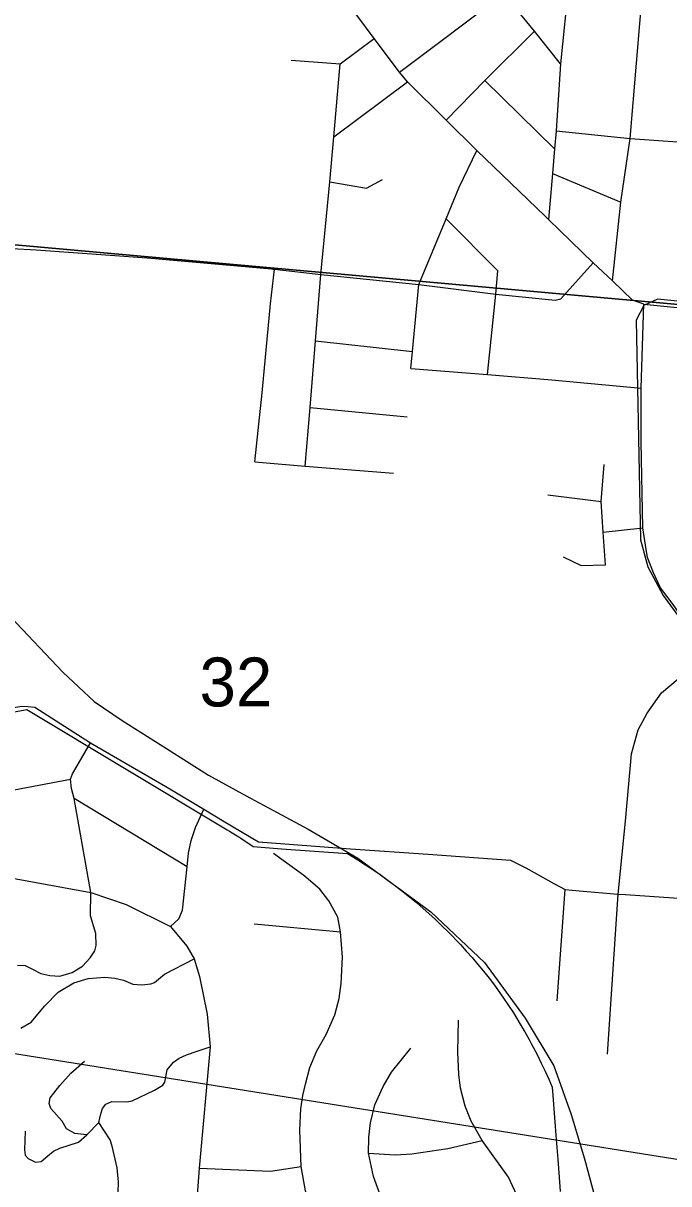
# Model space of a CAD drawing. Extents: x 0 to 34, y 0 to 22.
# Drawn here: x 7.286 to 7.838, y 16.149 to 17.141 of the extents above; entities that cross this region are included whole.
import ezdxf

# ---------------------------------------------------------------- set-up
doc = ezdxf.new("R2010")
doc.units = 0
for name, color, linetype in [('GM_X_City_Street', 7, 'Continuous'), ('GM_X_Corporation', 7, 'Continuous'), ('GM_X_County_Road', 7, 'Continuous'), ('GM_X_Rail_Line', 7, 'Continuous'), ('GM_X_Section', 7, 'Continuous'), ('GM_X_Section_Text', 7, 'Continuous'), ('GM_X_State_Route', 7, 'Continuous'), ('SH_Text', 7, 'Continuous')]:
    doc.layers.add(name, color=color, linetype=linetype)

msp = doc.modelspace()

# ---------------------------------------------------------------- linework, layer by layer
at = {"layer": 'GM_X_City_Street'}
for p, q in [((7.51532, 17.10956), (7.55715, 17.10645)), ((7.55199, 17.04406), (7.61492, 17.09112)), ((7.68107, 17.09212), (7.74065, 17.03371)), ((7.7388, 17.01252), (7.79727, 16.98814)), ((7.53616, 16.86947), (7.61911, 16.86058)), ((7.53157, 16.81266), (7.61446, 16.8047)), ((7.73481, 16.73799), (7.78045, 16.73214)), ((7.78205, 16.70614), (7.81605, 16.70967)), ((7.42639, 16.41983), (7.32984, 16.47827)), ((7.74284, 16.30544), (7.74954, 16.40042)), ((7.48369, 16.37107), (7.55766, 16.36424))]:
    msp.add_line(p, q, dxfattribs=at)
for points in [[(7.74582, 17.10655), (7.72338, 17.13426), (7.69725, 17.16653), (7.65761, 17.21715), (7.62474, 17.25859), (7.61315, 17.27463), (7.59254, 17.29971), (7.58023, 17.31598), (7.55509, 17.34949), (7.50926, 17.40665), (7.48027, 17.44644)], [(7.77465, 17.41698), (7.76349, 17.29985), (7.75806, 17.23874), (7.75554, 17.21033), (7.75285, 17.17688), (7.74582, 17.10655), (7.74198, 17.04901), (7.74065, 17.03371), (7.7388, 17.01252), (7.73539, 16.97335)], [(7.79013, 16.92089), (7.79727, 16.98814), (7.80529, 17.04266), (7.81622, 17.17162), (7.82746, 17.29367), (7.83759, 17.411)], [(7.60801, 17.09936), (7.69725, 17.16653), (7.75554, 17.21033)], [(7.5275, 16.76252), (7.53157, 16.81266), (7.53616, 16.86947), (7.54077, 16.92628), (7.54848, 17.00553), (7.55199, 17.04406), (7.55715, 17.10645), (7.58641, 17.12811)], [(7.64779, 17.05836), (7.68107, 17.09212), (7.72338, 17.13426)], [(7.74198, 17.04901), (7.80529, 17.04266), (7.86988, 17.0379), (7.93369, 17.03196), (7.99741, 17.02507)], [(6.87398, 17.04034), (6.87594, 17.04062), (6.89234, 17.04062), (6.93342, 17.03691), (6.98743, 17.03175), (7.00929, 17.02966), (7.07886, 17.02337), (7.10479, 17.02052), (7.12652, 17.01747), (7.14749, 17.00965), (7.16864, 16.99383), (7.19552, 16.96905), (7.21725, 16.95818), (7.23937, 16.95246), (7.25538, 16.94979), (7.29732, 16.94731), (7.39225, 16.94065), (7.49853, 16.93104), (7.49984, 16.93089)], [(7.61778, 16.84594), (7.61911, 16.86058), (7.62447, 16.91779), (7.64778, 16.97386), (7.65902, 17.00093), (7.67406, 17.03219)], [(7.54848, 17.00553), (7.57972, 17.00025), (7.59354, 17.00741)], [(7.68331, 16.84086), (7.69036, 16.90956), (7.69204, 16.92955), (7.64778, 16.97386)], [(7.48442, 16.76603), (7.49056, 16.8251), (7.49765, 16.90118), (7.50114, 16.93074)], [(7.49984, 16.93089), (7.50114, 16.93074), (7.54077, 16.92628), (7.62447, 16.91779), (7.69036, 16.90956), (7.74123, 16.90431), (7.74606, 16.9054), (7.77348, 16.93625)], [(7.81694, 16.90102), (7.93682, 16.8891), (7.98462, 16.88488), (8.04437, 16.87962), (8.11537, 16.87371), (8.17249, 16.86896), (8.22673, 16.86469), (8.28206, 16.85941), (8.33787, 16.85408), (8.37728, 16.85032), (8.391, 16.84899)], [(7.61778, 16.84594), (7.68331, 16.84086), (7.73817, 16.83632), (7.8148, 16.82907)], [(7.48442, 16.76603), (7.5275, 16.76252), (7.60301, 16.75637)], [(7.74808, 16.68491), (7.76347, 16.67748), (7.78417, 16.67801), (7.78205, 16.70614), (7.78045, 16.73214), (7.78311, 16.76399)], [(7.78593, 16.25962), (7.79493, 16.39645), (7.80114, 16.45906), (7.80629, 16.51637), (7.81208, 16.53698), (7.81981, 16.55115), (7.83204, 16.56854), (7.84621, 16.58077), (7.87319, 16.59913)], [(6.87585, 16.48336), (6.97046, 16.49893), (7.03039, 16.51025), (7.06372, 16.51668), (7.13408, 16.5302), (7.21462, 16.54449), (7.24901, 16.55139), (7.2852, 16.55714), (7.29024, 16.55685)], [(7.29024, 16.55685), (7.29629, 16.5565), (7.34384, 16.52595), (7.41019, 16.48732), (7.44063, 16.46921), (7.45817, 16.45877), (7.4874, 16.44118), (7.56608, 16.43524), (7.6324, 16.43086), (7.70279, 16.4255), (7.71598, 16.41897), (7.74003, 16.40553), (7.74954, 16.40042), (7.76162, 16.39947), (7.79493, 16.39645), (7.80136, 16.39612), (7.84228, 16.39327), (7.85843, 16.39216), (7.88993, 16.38985), (7.89517, 16.38998), (7.90065, 16.39199), (7.93809, 16.42333), (7.97955, 16.4558)], [(7.34407, 16.39783), (7.32984, 16.47827), (7.32763, 16.48693), (7.32683, 16.49492), (7.32849, 16.4995), (7.34384, 16.52595)], [(6.72775, 16.38441), (6.79183, 16.39661), (6.81886, 16.4019), (6.88791, 16.41554), (7.04306, 16.44285), (7.14606, 16.46187), (7.26181, 16.48265), (7.32683, 16.49492)], [(7.4122, 16.369), (7.41925, 16.37542), (7.42255, 16.38279), (7.42639, 16.41983), (7.42763, 16.43171), (7.42982, 16.44229), (7.43354, 16.4536), (7.44063, 16.46921)], [(7.5399, 16.11055), (7.53177, 16.13017), (7.52778, 16.14278), (7.524, 16.16379), (7.52294, 16.19468), (7.52379, 16.21297), (7.52546, 16.22452), (7.52757, 16.23397), (7.53135, 16.24848), (7.53744, 16.26256), (7.54543, 16.27663), (7.55279, 16.29344), (7.55635, 16.30731), (7.55825, 16.32013), (7.5593, 16.34261), (7.55766, 16.36424), (7.5553, 16.37686), (7.54753, 16.39094), (7.53976, 16.40082), (7.5261, 16.41259), (7.50034, 16.43133)], [(6.90173, 16.34609), (6.90994, 16.34281), (7.05572, 16.37132), (7.15994, 16.39025), (7.27409, 16.4109), (7.34407, 16.39783), (7.37444, 16.38782), (7.4122, 16.369), (7.42631, 16.35222), (7.43251, 16.34137), (7.43698, 16.32609), (7.44356, 16.29405), (7.44625, 16.26616), (7.43668, 16.16218), (7.43102, 16.08575)], [(7.28144, 16.33572), (7.28789, 16.33555), (7.29351, 16.33273), (7.30139, 16.32871), (7.30894, 16.32699), (7.31766, 16.32637), (7.328, 16.3295), (7.33689, 16.33496), (7.34353, 16.342), (7.3475, 16.34798), (7.34875, 16.35251), (7.34828, 16.36278), (7.34375, 16.37812), (7.34407, 16.39783)], [(7.28429, 16.28199), (7.29305, 16.28712), (7.30472, 16.30098), (7.31604, 16.31278), (7.32957, 16.32075), (7.34175, 16.32449), (7.35605, 16.32545), (7.36459, 16.32477), (7.3719, 16.32297), (7.38013, 16.31969), (7.38775, 16.31911), (7.39543, 16.32001), (7.39855, 16.32103), (7.40709, 16.32804), (7.43251, 16.34137)], [(7.71186, 16.13176), (7.70116, 16.15456), (7.67872, 16.18582), (7.66932, 16.20239), (7.66426, 16.2152), (7.66026, 16.23059), (7.65884, 16.24242), (7.65792, 16.26139), (7.65834, 16.28885)], [(7.28783, 16.19398), (7.28733, 16.17791), (7.288, 16.17327), (7.29048, 16.17046), (7.29678, 16.16731), (7.30158, 16.16797), (7.30738, 16.17277), (7.31227, 16.17683), (7.31768, 16.1795), (7.33354, 16.18461), (7.34066, 16.19083), (7.35096, 16.20144), (7.35258, 16.20884), (7.35393, 16.21336), (7.35702, 16.21712), (7.362, 16.21937), (7.37501, 16.21888), (7.37934, 16.21976), (7.39864, 16.22892), (7.40573, 16.23326), (7.4075, 16.23572), (7.40934, 16.24628), (7.41485, 16.25298), (7.41961, 16.2563), (7.42592, 16.25916), (7.43498, 16.26231), (7.44625, 16.26616)], [(7.59158, 16.13936), (7.58576, 16.15511), (7.58153, 16.17508), (7.58167, 16.18879), (7.58313, 16.20103), (7.58707, 16.21649), (7.59392, 16.23208), (7.60121, 16.24433), (7.61768, 16.26489)], [(7.34066, 16.19083), (7.33031, 16.19191), (7.32342, 16.19578), (7.31954, 16.20246), (7.30985, 16.21324), (7.30834, 16.21754), (7.30941, 16.2225), (7.31243, 16.22638), (7.3176, 16.23306), (7.32708, 16.24362), (7.33861, 16.25385)], [(7.34936, 15.91821), (7.3635, 16.08465), (7.36678, 16.13044), (7.36753, 16.14179), (7.36769, 16.15041), (7.36662, 16.16258), (7.36239, 16.18098), (7.36062, 16.1864), (7.35096, 16.20144)], [(7.58153, 16.17508), (7.60441, 16.17379), (7.61859, 16.17466), (7.64934, 16.17896), (7.67872, 16.18582)], [(7.43668, 16.16218), (7.49782, 16.15983), (7.524, 16.16379)]]:
    msp.add_lwpolyline(points, dxfattribs=at)
at = {"layer": 'GM_X_Corporation'}
msp.add_lwpolyline([(7.09806, 16.51957), (7.28793, 16.5541), (7.28942, 16.55437), (7.4607, 16.45143), (7.4626, 16.45029), (7.465, 16.44885), (7.46909, 16.4464), (7.47061, 16.44548), (7.47237, 16.44443), (7.48295, 16.43715), (7.50713, 16.43539), (7.56342, 16.43129), (7.5725, 16.42577), (7.57888, 16.42169), (7.5852, 16.41751), (7.59144, 16.41322), (7.59761, 16.40882), (7.60369, 16.40431), (7.6097, 16.3997), (7.61659, 16.3942), (7.62242, 16.38936), (7.62816, 16.38435), (7.63323, 16.37992), (7.63881, 16.3748), (7.6443, 16.36958), (7.64969, 16.36426), (7.66004, 16.35352), (7.66516, 16.34793), (7.67017, 16.34225), (7.67509, 16.33649), (7.6799, 16.33064), (7.68462, 16.32471), (7.68922, 16.31869), (7.69706, 16.30761), (7.70128, 16.30132), (7.7054, 16.29496), (7.71126, 16.28545), (7.71328, 16.28204), (7.71509, 16.27892), (7.71881, 16.27231), (7.72062, 16.269), (7.72241, 16.26565), (7.7259, 16.25892), (7.72927, 16.25214), (7.73171, 16.24702), (7.73252, 16.24529), (7.73565, 16.2384), (7.73866, 16.23144), (7.7392, 16.22441), (7.74064, 16.20557), (7.74209, 16.1867), (7.7434, 16.16971), (7.74456, 16.15461), (7.7455, 16.14234)], dxfattribs=at)
at = {"layer": 'GM_X_County_Road'}
msp.add_line((7.8148, 16.82907), (7.81694, 16.90102), dxfattribs=at)
for points in [[(7.81694, 16.90102), (7.80727, 16.9044), (7.79013, 16.92089), (7.77348, 16.93625), (7.73539, 16.97335), (7.73247, 16.97619), (7.67406, 17.03219), (7.64779, 17.05836), (7.61492, 17.09112), (7.60801, 17.09936), (7.58641, 17.12811), (7.57073, 17.14902), (7.5382, 17.18996), (7.50467, 17.23324), (7.46774, 17.28045), (7.42178, 17.33945), (7.41993, 17.34179)], [(8.0805, 16.29774), (8.05901, 16.3344), (8.04707, 16.35635), (8.03514, 16.37829), (8.01143, 16.40965), (7.97955, 16.4558), (7.94074, 16.50505), (7.90814, 16.55212), (7.87319, 16.59913), (7.84196, 16.64408), (7.83119, 16.6583), (7.82522, 16.67114), (7.82017, 16.68444), (7.81834, 16.69487), (7.81605, 16.70967), (7.8148, 16.78327), (7.8148, 16.82907)]]:
    msp.add_lwpolyline(points, dxfattribs=at)
at = {"layer": 'GM_X_Rail_Line'}
for points in [[(7.81688, 16.8999), (7.81047, 16.88737), (7.81397, 16.6995), (7.82038, 16.6764), (7.8335, 16.65195), (8.0389, 16.37194), (8.25793, 15.99507), (8.72815, 15.17265), (8.83277, 15.03655), (8.84561, 15.01602), (8.84689, 15.00704)], [(8.9, 16.31162), (8.87979, 16.33238), (8.67814, 16.59957), (8.38192, 16.84958), (7.8287, 16.90508), (7.81688, 16.8999)], [(7.27552, 16.63357), (7.32014, 16.58645), (7.34699, 16.56123), (7.37091, 16.54506), (7.40866, 16.52105), (7.44456, 16.49818), (7.47702, 16.48053), (7.52988, 16.45222), (7.57227, 16.42745), (7.63476, 16.3814), (7.6808, 16.33809), (7.7154, 16.29054), (7.73999, 16.24982), (7.7548, 16.20815), (7.76631, 16.17032), (7.77508, 16.13743)]]:
    msp.add_lwpolyline(points, dxfattribs=at)
at = {"layer": 'GM_X_Section'}
for points in [[(7.09659, 17.98301), (8.0955, 17.8939), (8.00161, 16.88676), (7.0031, 16.97632)], [(7.0031, 16.97632), (8.00161, 16.88676), (7.90346, 15.87364), (6.90635, 15.9571)]]:
    msp.add_lwpolyline(points, close=True, dxfattribs=at)
at = {"layer": 'GM_X_State_Route'}
msp.add_lwpolyline([(7.09806, 16.51957), (7.28793, 16.5541), (7.28942, 16.55437), (7.4607, 16.45143), (7.4626, 16.45029), (7.465, 16.44885), (7.46909, 16.4464), (7.47061, 16.44548), (7.47237, 16.44443), (7.48295, 16.43715), (7.50713, 16.43539), (7.56342, 16.43129), (7.5725, 16.42577), (7.57888, 16.42169), (7.5852, 16.41751), (7.59144, 16.41322), (7.59761, 16.40882), (7.60369, 16.40431), (7.6097, 16.3997), (7.61659, 16.3942), (7.62242, 16.38936), (7.62816, 16.38435), (7.63323, 16.37992), (7.63881, 16.3748), (7.6443, 16.36958), (7.64969, 16.36426), (7.66004, 16.35352), (7.66516, 16.34793), (7.67017, 16.34225), (7.67509, 16.33649), (7.6799, 16.33064), (7.68462, 16.32471), (7.68922, 16.31869), (7.69706, 16.30761), (7.70128, 16.30132), (7.7054, 16.29496), (7.71126, 16.28545), (7.71328, 16.28204), (7.71509, 16.27892), (7.71881, 16.27231), (7.72062, 16.269), (7.72241, 16.26565), (7.7259, 16.25892), (7.72927, 16.25214), (7.73171, 16.24702), (7.73252, 16.24529), (7.73565, 16.2384), (7.73866, 16.23144), (7.7392, 16.22441), (7.74064, 16.20557), (7.74209, 16.1867), (7.7434, 16.16971), (7.74456, 16.15461), (7.7455, 16.14234)], dxfattribs=at)
at = {"layer": 'SH_Text'}
msp.add_lwpolyline([(5.55979, 16.53453), (9.34596, 15.93059), (10.72957, 15.93898), (10.7249, 15.65405), (9.36841, 15.65826)], close=True, dxfattribs=at)

# ---------------------------------------------------------------- texts
at = {"layer": 'GM_X_Section_Text'}
msp.add_text('32', height=0.041856, rotation=0.00001, dxfattribs=at).set_placement((7.43701, 16.557))

doc.saveas('drawing.dxf')
